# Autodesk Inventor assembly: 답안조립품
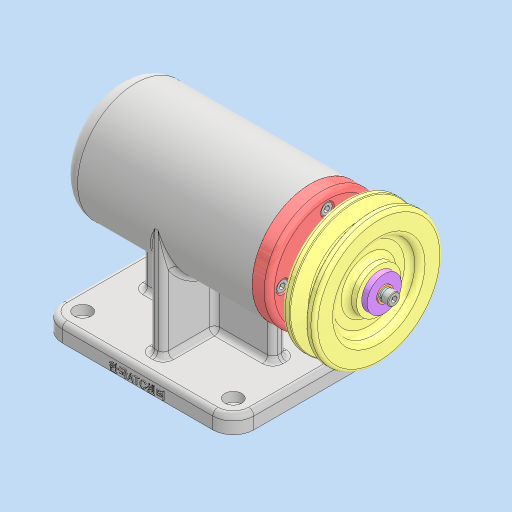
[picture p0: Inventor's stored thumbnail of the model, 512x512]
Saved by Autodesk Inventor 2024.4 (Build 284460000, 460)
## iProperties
Created: 2026-08
Part Number: 답안조립품
Document SubType Name: Assembly
Designer: home
Author: home
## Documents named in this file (13)
- C:\Users\kimgi\Desktop\760803V1002\답안조립품.iam
- C:\Users\kimgi\Desktop\760803V1002\본체.ipt
- C:\Users\kimgi\Desktop\760803V1002\축.ipt
- C:\Users\kimgi\Desktop\760803V1002\깊은 홈 볼 베어링 6004.ipt
- C:\Users\kimgi\Desktop\760803V1002\평행 키 5x5x16.ipt
- C:\Users\kimgi\Desktop\760803V1002\V 벨트 풀리.ipt
- C:\Users\kimgi\Desktop\760803V1002\엔드 캡.ipt
- C:\Users\kimgi\Desktop\760803V1002\평 와셔 M4.ipt
- C:\Users\kimgi\Desktop\760803V1002\스프링 와셔 M4.ipt
- C:\Users\kimgi\Desktop\760803V1002\6각 구멍붙이 볼트 M4x12.ipt
- C:\Users\kimgi\Desktop\760803V1002\어댑터 슬리브.ipt
- C:\Users\kimgi\Desktop\760803V1002\스러스트 볼 베어링 51202.ipt
- C:\Users\kimgi\Desktop\760803V1002\커버.ipt
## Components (7 placed, 2 different names)
1. V 벨트 풀리:1
2. 6각 구멍붙이 볼트 M4x12:1
3. 6각 구멍붙이 볼트 M4x12:2
4. 6각 구멍붙이 볼트 M4x12:3
5. 6각 구멍붙이 볼트 M4x12:4
6. 6각 구멍붙이 볼트 M4x12:5
7. 6각 구멍붙이 볼트 M4x12:6
